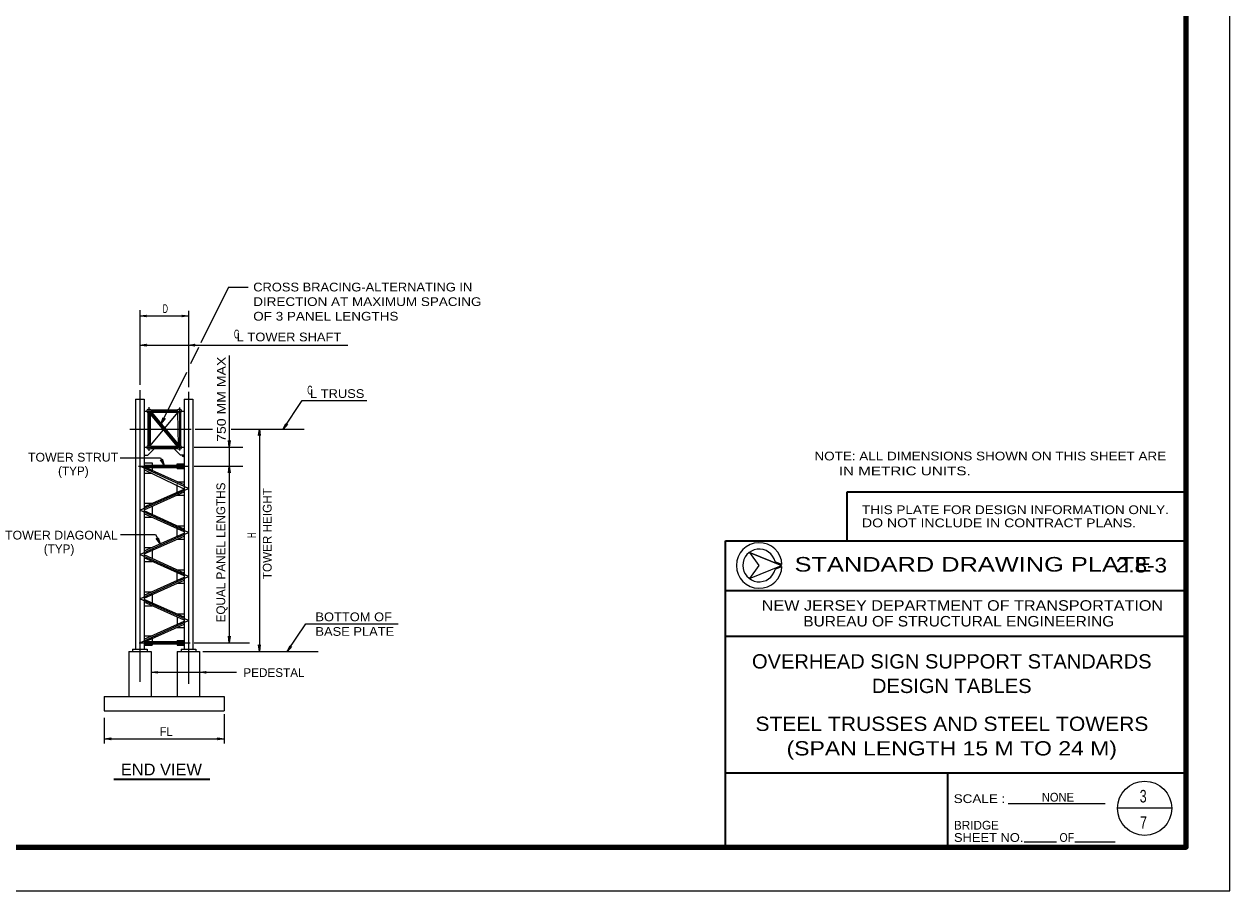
# Model space of a CAD drawing. Extents: x 312601.858 to 312602.699, y 144420.11 to 144420.704.
# Drawn here: x 312602.2859 to 312602.6989, y 144420.1096 to 144420.4066 of the extents above; entities that cross this region are included whole.
import ezdxf
from ezdxf.enums import TextEntityAlignment as Align

# ---------------------------------------------------------------- set-up
doc = ezdxf.new("R2010")
doc.units = 0
doc.header["$LTSCALE"] = 0.0012
doc.header["$PDMODE"] = 32
doc.header["$PDSIZE"] = 0.0006
doc.linetypes.add('DOT_DASHED', pattern=[7.7, 5, -1.2, 0.3, -1.2])
doc.linetypes.add('LONG_DASHED', pattern=[7.5, 6, -1.5])
for name, color, linetype, lineweight in [('1', 7, 'Continuous', 25), ('2', 7, 'Continuous', 13), ('39', 7, 'Continuous', 13)]:
    doc.layers.add(name, color=color, linetype=linetype, lineweight=lineweight)
doc.layers.add('51', color=7, linetype='Continuous')

msp = doc.modelspace()

# ---------------------------------------------------------------- hatches: boundary and pattern name
at = {"layer": '39'}
for points in [[(312602.3276, 144420.3066), (312602.3278, 144420.3063), (312602.3256, 144420.3066), (312602.3278, 144420.3069)], [(312602.3402, 144420.3066), (312602.34, 144420.3069), (312602.3422, 144420.3066), (312602.34, 144420.3063)], [(312602.3276, 144420.2966), (312602.3278, 144420.2963), (312602.3256, 144420.2966), (312602.3278, 144420.2969)], [(312602.3442, 144420.2966), (312602.3444, 144420.2963), (312602.3422, 144420.2966), (312602.3444, 144420.2969)], [(312602.3338, 144420.2715), (312602.3342, 144420.2715), (312602.3329, 144420.2697), (312602.3336, 144420.2718)], [(312602.3757, 144420.2695), (312602.3761, 144420.2695), (312602.3746, 144420.2678), (312602.3756, 144420.2698)], [(312602.333, 144420.2573), (312602.3332, 144420.2576), (312602.3339, 144420.2555), (312602.3326, 144420.2573)], [(312602.333, 144420.2573), (312602.3332, 144420.2576), (312602.3339, 144420.2555), (312602.3326, 144420.2573)], [(312602.3316, 144420.2303), (312602.3318, 144420.2306), (312602.3325, 144420.2285), (312602.3312, 144420.2303)], [(312602.3771, 144420.1933), (312602.3775, 144420.1933), (312602.376, 144420.1916), (312602.377, 144420.1936)], [(312602.3314, 144420.1845), (312602.3316, 144420.1842), (312602.3294, 144420.1845), (312602.3316, 144420.1848)], [(312602.348, 144420.1845), (312602.3482, 144420.1842), (312602.346, 144420.1845), (312602.3482, 144420.1848)]]:
    msp.add_hatch(color=256, dxfattribs=at).paths.add_polyline_path(points)

# ---------------------------------------------------------------- linework, layer by layer
at = {"layer": '1', "lineweight": 13}
for p, q in [((312602.3559, 144420.3165), (312602.3465, 144420.2974)), ((312602.3559, 144420.3165), (312602.3627, 144420.3165)), ((312602.3256, 144420.3086), (312602.3256, 144420.283)), ((312602.3422, 144420.3084), (312602.3422, 144420.2822)), ((312602.3457, 144420.2958), (312602.3429, 144420.2902)), ((312602.3415, 144420.2872), (312602.3329, 144420.2697)), ((312602.3221, 144420.2678), (312602.33, 144420.2678)), ((312602.3445, 144420.2678), (312602.3505, 144420.2678)), ((312602.3568, 144420.2678), (312602.3819, 144420.2678)), ((312602.3571, 144420.2678), (312602.3585, 144420.2678)), ((312602.3665, 144420.2678), (312602.3665, 144420.1916)), ((312602.3442, 144420.2616), (312602.3608, 144420.2616)), ((312602.3326, 144420.258), (312602.3339, 144420.2555)), ((312602.3442, 144420.2551), (312602.3608, 144420.2551)), ((312602.3189, 144420.2317), (312602.3309, 144420.2317)), ((312602.3309, 144420.2317), (312602.3325, 144420.2286)), ((312602.5432, 144420.2198), (312602.5455, 144420.2208)), ((312602.3442, 144420.1946), (312602.3631, 144420.1946)), ((312602.3471, 144420.1916), (312602.3866, 144420.1916)), ((312602.3294, 144420.1845), (312602.3587, 144420.1845)), ((312602.3544, 144420.1702), (312602.3544, 144420.1601)), ((312602.3134, 144420.1689), (312602.3134, 144420.1601)), ((312602.3544, 144420.1694), (312602.3544, 144420.1685)), ((312602.3134, 144420.1617), (312602.3544, 144420.1617)), ((312602.6285, 144420.1264), (312602.6395, 144420.1264)), ((312602.6458, 144420.1264), (312602.6596, 144420.1264))]:
    msp.add_line(p, q, dxfattribs=at)
at = {"layer": '1'}
for p, q in [((312602.3241, 144420.2781), (312602.3241, 144420.1924)), ((312602.3241, 144420.2781), (312602.3271, 144420.2781)), ((312602.3271, 144420.2781), (312602.3271, 144420.1924)), ((312602.3407, 144420.2781), (312602.3407, 144420.1924)), ((312602.3407, 144420.2781), (312602.3437, 144420.2781)), ((312602.3437, 144420.2781), (312602.3437, 144420.1924)), ((312602.3283, 144420.2734), (312602.3283, 144420.2622)), ((312602.3291, 144420.2734), (312602.3291, 144420.2622)), ((312602.3293, 144420.2744), (312602.3385, 144420.2744)), ((312602.3296, 144420.2736), (312602.3387, 144420.2627)), ((312602.3395, 144420.2734), (312602.3395, 144420.2622)), ((312602.3291, 144420.2729), (312602.3382, 144420.262)), ((312602.3293, 144420.262), (312602.3385, 144420.262)), ((312602.3293, 144420.2612), (312602.3385, 144420.2612)), ((312602.3271, 144420.2563), (312602.3298, 144420.2563)), ((312602.3271, 144420.2555), (312602.3407, 144420.2555)), ((312602.3271, 144420.2547), (312602.3407, 144420.2547)), ((312602.3271, 144420.2527), (312602.3297, 144420.2527)), ((312602.3407, 144420.2487), (312602.3275, 144420.2547)), ((312602.3298, 144420.2563), (312602.3298, 144420.2555)), ((312602.3298, 144420.2547), (312602.3298, 144420.2537)), ((312602.3383, 144420.2559), (312602.3407, 144420.2559)), ((312602.3383, 144420.2555), (312602.3383, 144420.2559)), ((312602.3383, 144420.2543), (312602.3383, 144420.2547)), ((312602.3383, 144420.2543), (312602.3407, 144420.2543)), ((312602.3383, 144420.2498), (312602.3407, 144420.2498)), ((312602.3383, 144420.2462), (312602.3383, 144420.2488)), ((312602.3271, 144420.2402), (312602.3407, 144420.2463)), ((312602.3383, 144420.2452), (312602.3407, 144420.2452)), ((312602.3271, 144420.2424), (312602.3298, 144420.2424)), ((312602.3298, 144420.2414), (312602.3298, 144420.2386)), ((312602.3407, 144420.2336), (312602.3271, 144420.2398)), ((312602.3407, 144420.2326), (312602.3271, 144420.2388)), ((312602.3271, 144420.2376), (312602.3298, 144420.2376)), ((312602.3271, 144420.2261), (312602.3407, 144420.2322)), ((312602.3383, 144420.2347), (312602.3407, 144420.2347)), ((312602.3383, 144420.2311), (312602.3383, 144420.2337)), ((312602.3271, 144420.2251), (312602.3407, 144420.2312)), ((312602.3383, 144420.2301), (312602.3407, 144420.2301)), ((312602.3271, 144420.2273), (312602.3298, 144420.2273)), ((312602.3407, 144420.2185), (312602.3271, 144420.2247)), ((312602.3407, 144420.2175), (312602.3271, 144420.2237)), ((312602.3298, 144420.2263), (312602.3298, 144420.2235)), ((312602.3271, 144420.2225), (312602.3298, 144420.2225)), ((312602.3383, 144420.2196), (312602.3407, 144420.2196)), ((312602.3271, 144420.2109), (312602.3407, 144420.2171)), ((312602.3271, 144420.2099), (312602.3407, 144420.2161)), ((312602.3383, 144420.216), (312602.3383, 144420.2186)), ((312602.3271, 144420.2121), (312602.3298, 144420.2121)), ((312602.3383, 144420.215), (312602.3407, 144420.215)), ((312602.3407, 144420.2034), (312602.3271, 144420.2095)), ((312602.3407, 144420.2024), (312602.3271, 144420.2085)), ((312602.3271, 144420.2073), (312602.3298, 144420.2073)), ((312602.3298, 144420.2111), (312602.3298, 144420.2083)), ((312602.3383, 144420.2045), (312602.3407, 144420.2045)), ((312602.3383, 144420.2035), (312602.3383, 144420.2009)), ((312602.3271, 144420.1958), (312602.3407, 144420.202)), ((312602.3275, 144420.195), (312602.3407, 144420.201)), ((312602.3383, 144420.1999), (312602.3407, 144420.1999)), ((312602.3271, 144420.197), (312602.3298, 144420.197)), ((312602.3271, 144420.195), (312602.3407, 144420.195)), ((312602.3298, 144420.196), (312602.3298, 144420.195)), ((312602.3383, 144420.1954), (312602.3407, 144420.1954)), ((312602.3383, 144420.1954), (312602.3383, 144420.195)), ((312602.3218, 144420.1916), (312602.3218, 144420.1762)), ((312602.3218, 144420.1916), (312602.3294, 144420.1916)), ((312602.3231, 144420.1924), (312602.3231, 144420.1916)), ((312602.3231, 144420.1924), (312602.3281, 144420.1924)), ((312602.3271, 144420.1942), (312602.3407, 144420.1942)), ((312602.3271, 144420.1938), (312602.3298, 144420.1938)), ((312602.3281, 144420.1924), (312602.3281, 144420.1916)), ((312602.3294, 144420.1916), (312602.3294, 144420.1762)), ((312602.3298, 144420.1942), (312602.3298, 144420.1938)), ((312602.3383, 144420.1942), (312602.3383, 144420.1938)), ((312602.3383, 144420.1938), (312602.3407, 144420.1938)), ((312602.3384, 144420.1916), (312602.3384, 144420.1762)), ((312602.3384, 144420.1916), (312602.346, 144420.1916)), ((312602.3397, 144420.1924), (312602.3397, 144420.1916)), ((312602.3397, 144420.1924), (312602.3447, 144420.1924)), ((312602.3447, 144420.1924), (312602.3447, 144420.1916)), ((312602.346, 144420.1916), (312602.346, 144420.1762)), ((312602.3134, 144420.1762), (312602.3134, 144420.1713)), ((312602.3134, 144420.1762), (312602.3544, 144420.1762)), ((312602.3544, 144420.1762), (312602.3544, 144420.1713)), ((312602.3134, 144420.1713), (312602.3544, 144420.1713))]:
    msp.add_line(p, q, dxfattribs=at)
at = {"layer": '1', "linetype": 'DOT_DASHED', "lineweight": 13}
for p, q in [((312602.3256, 144420.2812), (312602.3256, 144420.1705)), ((312602.3422, 144420.2806), (312602.3422, 144420.1707)), ((312602.3271, 144420.274), (312602.3407, 144420.274)), ((312602.3287, 144420.2753), (312602.3287, 144420.2604)), ((312602.3287, 144420.274), (312602.3391, 144420.2616)), ((312602.3391, 144420.2752), (312602.3391, 144420.2605)), ((312602.3236, 144420.2678), (312602.3431, 144420.2678)), ((312602.3271, 144420.2616), (312602.3407, 144420.2616)), ((312602.3251, 144420.2551), (312602.3423, 144420.2551)), ((312602.3253, 144420.1946), (312602.3428, 144420.1946))]:
    msp.add_line(p, q, dxfattribs=at)
at = {"layer": '1', "linetype": 'LONG_DASHED', "lineweight": 13}
msp.add_line((312602.3291, 144420.2621), (312602.3386, 144420.2735), dxfattribs=at)
at = {"layer": '1', "lineweight": 13}
for points in [[(312602.3562, 144420.293), (312602.3562, 144420.2551), (312602.3562, 144420.1946)], [(312602.5453, 144420.2211), (312602.5344, 144420.2256), (312602.5453, 144420.2211)], [(312602.5455, 144420.2214), (312602.5432, 144420.2224), (312602.5431, 144420.2224)]]:
    msp.add_lwpolyline(points, dxfattribs=at)
at = {"layer": '1'}
for points in [[(312602.3293, 144420.2736), (312602.3385, 144420.2736), (312602.3387, 144420.2622)], [(312602.3271, 144420.2589), (312602.3283, 144420.2589), (312602.3306, 144420.2612)], [(312602.3407, 144420.2589), (312602.3395, 144420.2589), (312602.3372, 144420.2612)], [(312602.3271, 144420.2412), (312602.3407, 144420.2473), (312602.3271, 144420.2539)]]:
    msp.add_lwpolyline(points, dxfattribs=at)
at = {"layer": '1', "lineweight": 13}
for points in [[(312602.3662, 144420.2656), (312602.3665, 144420.2678), (312602.3668, 144420.2656), (312602.3665, 144420.2658)], [(312602.3565, 144420.2639), (312602.3562, 144420.2616), (312602.3559, 144420.2639), (312602.3562, 144420.2636)], [(312602.3559, 144420.2529), (312602.3562, 144420.2551), (312602.3565, 144420.2529), (312602.3562, 144420.2531)], [(312602.5453, 144420.2211), (312602.5344, 144420.2256), (312602.5376, 144420.2211), (312602.5344, 144420.2166)], [(312602.5376, 144420.2211), (312602.5344, 144420.2166), (312602.5453, 144420.2211), (312602.5344, 144420.2256)], [(312602.3565, 144420.1969), (312602.3562, 144420.1946), (312602.3559, 144420.1969), (312602.3562, 144420.1966)], [(312602.3668, 144420.1939), (312602.3665, 144420.1916), (312602.3662, 144420.1939), (312602.3665, 144420.1936)], [(312602.3157, 144420.1614), (312602.3134, 144420.1617), (312602.3157, 144420.162), (312602.3154, 144420.1617)], [(312602.3522, 144420.162), (312602.3544, 144420.1617), (312602.3522, 144420.1614), (312602.3524, 144420.1617)]]:
    msp.add_lwpolyline(points, close=True, dxfattribs=at)
at = {"layer": '1', "linetype": 'DOT_DASHED', "lineweight": 13}
msp.add_lwpolyline([(312602.3256, 144420.1946), (312602.3422, 144420.2022), (312602.3256, 144420.2097), (312602.3422, 144420.2173), (312602.3256, 144420.2249), (312602.3422, 144420.2324), (312602.3256, 144420.24), (312602.3422, 144420.2475), (312602.3256, 144420.2551)], dxfattribs=at)
at = {"layer": '1'}
for centre in [(312602.3287, 144420.274), (312602.3391, 144420.274), (312602.3287, 144420.2616), (312602.3391, 144420.2616)]:
    msp.add_circle(centre, 0.0007, dxfattribs=at)
at = {"layer": '1', "lineweight": 13}
for radius, start, end in [(0.0078026, 2.21392, 357.78608), (0.0056, 13.69411, 346.30589)]:
    msp.add_arc((312602.5377, 144420.2211), radius, start, end, dxfattribs=at)
at = {"layer": '1'}
msp.add_point((312602.3405, 144420.2586), dxfattribs=at)
at = {"layer": '2'}
for p, q in [((312602.3256, 144420.3066), (312602.3422, 144420.3066)), ((312602.3188, 144420.258), (312602.3326, 144420.258))]:
    msp.add_line(p, q, dxfattribs=at)
at = {"layer": '2', "lineweight": 35}
msp.add_line((312602.3167, 144420.1479), (312602.3495, 144420.1479), dxfattribs=at)
at = {"layer": '2'}
for points in [[(312602.3256, 144420.2966), (312602.3422, 144420.2966), (312602.3968, 144420.2966)], [(312602.3746, 144420.2678), (312602.3812, 144420.2776), (312602.4033, 144420.2776)], [(312602.376, 144420.1916), (312602.3824, 144420.2011), (312602.414, 144420.2011)]]:
    msp.add_lwpolyline(points, dxfattribs=at)
at = {"layer": '39', "lineweight": 35}
for p, q in [((312602.5678, 144420.2463), (312602.6839, 144420.2463)), ((312602.5678, 144420.2296), (312602.5678, 144420.2463)), ((312602.5261, 144420.1246), (312602.5261, 144420.2296)), ((312602.5261, 144420.2296), (312602.6839, 144420.2296)), ((312602.6839, 144420.2296), (312602.6839, 144420.1246)), ((312602.5261, 144420.2125), (312602.6839, 144420.2125)), ((312602.5261, 144420.1969), (312602.6839, 144420.1969)), ((312602.5261, 144420.15), (312602.6839, 144420.15)), ((312602.6023, 144420.1249), (312602.6023, 144420.15))]:
    msp.add_line(p, q, dxfattribs=at)
at = {"layer": '39'}
for p, q in [((312602.6023, 144420.15), (312602.6839, 144420.15)), ((312602.623, 144420.1396), (312602.6562, 144420.1396))]:
    msp.add_line(p, q, dxfattribs=at)
at = {"layer": '39', "lineweight": 25}
for p, q in [((312602.679, 144420.1379), (312602.6604, 144420.1379)), ((312602.4521, 144420.1246), (312602.6839, 144420.1246))]:
    msp.add_line(p, q, dxfattribs=at)
msp.add_lwpolyline([(312601.8579, 144420.1096), (312602.6989, 144420.1096), (312602.6989, 144420.7036)], dxfattribs=at)
at = {"layer": '39', "lineweight": 158}
msp.add_lwpolyline([(312601.9089, 144420.1246), (312602.6839, 144420.1246), (312602.6839, 144420.6646)], dxfattribs=at)
at = {"layer": '39'}
for points in [[(312602.3276, 144420.3066), (312602.3278, 144420.3063), (312602.3256, 144420.3066), (312602.3278, 144420.3069)], [(312602.3402, 144420.3066), (312602.34, 144420.3069), (312602.3422, 144420.3066), (312602.34, 144420.3063)], [(312602.3276, 144420.2966), (312602.3278, 144420.2963), (312602.3256, 144420.2966), (312602.3278, 144420.2969)], [(312602.3442, 144420.2966), (312602.3444, 144420.2963), (312602.3422, 144420.2966), (312602.3444, 144420.2969)], [(312602.3338, 144420.2715), (312602.3342, 144420.2715), (312602.3329, 144420.2697), (312602.3336, 144420.2718)], [(312602.3757, 144420.2695), (312602.3761, 144420.2695), (312602.3746, 144420.2678), (312602.3756, 144420.2698)], [(312602.333, 144420.2573), (312602.3332, 144420.2576), (312602.3339, 144420.2555), (312602.3326, 144420.2573)], [(312602.333, 144420.2573), (312602.3332, 144420.2576), (312602.3339, 144420.2555), (312602.3326, 144420.2573)], [(312602.3316, 144420.2303), (312602.3318, 144420.2306), (312602.3325, 144420.2285), (312602.3312, 144420.2303)], [(312602.5453, 144420.2211), (312602.5344, 144420.2256), (312602.5376, 144420.2211), (312602.5344, 144420.2166)], [(312602.3771, 144420.1933), (312602.3775, 144420.1933), (312602.376, 144420.1916), (312602.377, 144420.1936)], [(312602.3314, 144420.1845), (312602.3316, 144420.1842), (312602.3294, 144420.1845), (312602.3316, 144420.1848)], [(312602.348, 144420.1845), (312602.3482, 144420.1842), (312602.346, 144420.1845), (312602.3482, 144420.1848)]]:
    msp.add_lwpolyline(points, close=True, dxfattribs=at)
at = {"layer": '39', "lineweight": 25}
msp.add_circle((312602.6697, 144420.1379), 0.0093005, dxfattribs=at)

# ---------------------------------------------------------------- texts
at = {"layer": '1'}
for s, width, p in [('NOTE: ALL DIMENSIONS SHOWN ON THIS SHEET ARE', 1.15, (312602.5566, 144420.2571)), ('     IN METRIC UNITS.', 1.3, (312602.5577, 144420.252)), ('TOWER DIAGONAL', 1.05, (312602.2794, 144420.23))]:
    msp.add_text(s, height=0.003, dxfattribs=dict(at, width=width)).set_placement(p)
msp.add_text('TOWER HEIGHT', height=0.003, rotation=90, dxfattribs=at).set_placement((312602.3707, 144420.232), align=Align.CENTER)
at = {"layer": '1', "width": 0.95}
for s, p in [('FL', (312602.3346, 144420.1627)), ('NONE', (312602.64, 144420.1402))]:
    msp.add_text(s, height=0.003, dxfattribs=at).set_placement(p, align=Align.CENTER)
at = {"layer": '2'}
for s, width, p in [('CROSS BRACING-ALTERNATING IN', 1.1, (312602.3644, 144420.315)), ('DIRECTION AT MAXIMUM SPACING', 1.15, (312602.3644, 144420.31)), ('OF 3 PANEL LENGTHS', 1.15, (312602.3644, 144420.305)), ('THIS PLATE FOR DESIGN INFORMATION ONLY.', 1.15, (312602.5729, 144420.2387)), ('DO NOT INCLUDE IN CONTRACT PLANS.', 1.2, (312602.5729, 144420.2342)), ('BOTTOM OF', 1.1, (312602.3857, 144420.202)), ('BASE PLATE', 1.1, (312602.3857, 144420.197))]:
    msp.add_text(s, height=0.003, dxfattribs=dict(at, width=width)).set_placement(p)
for s, height, width, p in [('D', 0.003, 0.6, (312602.3343, 144420.3076)), ('C', 0.003, 0.6, (312602.3587, 144420.2989)), ('L TOWER SHAFT', 0.003, 1.1, (312602.37665, 144420.2979)), ('C', 0.003, 0.6, (312602.3838, 144420.2797)), ('L TRUSS', 0.003, 1.1, (312602.39315, 144420.2785)), ('TOWER STRUT', 0.003, 1.05, (312602.3027, 144420.2567)), ('2.8-3', 0.005, 1.15, (312602.6686, 144420.2187)), ('OVERHEAD SIGN SUPPORT STANDARDS', 0.0049, 1.05, (312602.60365, 144420.1858)), ('DESIGN TABLES', 0.0049, 1.05, (312602.60365, 144420.1774)), ('STEEL TRUSSES AND STEEL TOWERS', 0.0049, 1.1, (312602.6037, 144420.1644)), ('(SPAN LENGTH 15 M TO 24 M)', 0.0049, 1.2, (312602.60365, 144420.156)), ('END VIEW', 0.004, 1.05, (312602.33295, 144420.1492))]:
    msp.add_text(s, height=height, dxfattribs=dict(at, width=width)).set_placement(p, align=Align.CENTER)
for s, height, width, p in [('750 MM MAX', 0.003, 1.2, (312602.355, 144420.27805)), ('H', 0.002998, 0.6, (312602.3654, 144420.23145))]:
    msp.add_text(s, height=height, rotation=90, dxfattribs=dict(at, width=width)).set_placement(p, align=Align.CENTER)
for s, p in [('(TYP)', (312602.3028, 144420.252)), ('(TYP)', (312602.2979, 144420.2253)), ('PEDESTAL', (312602.3715, 144420.1829))]:
    msp.add_text(s, height=0.003, dxfattribs=at).set_placement(p, align=Align.CENTER)
msp.add_text('EQUAL PANEL LENGTHS', height=0.003, rotation=90, dxfattribs=at).set_placement((312602.3548, 144420.22555), align=Align.CENTER)
at = {"layer": '39'}
for s, height, width, p in [('STANDARD DRAWING PLATE       ', 0.005, 1.3, (312602.61935, 144420.219)), ('NEW JERSEY DEPARTMENT OF TRANSPORTATION', 0.003599, 1.15, (312602.6073, 144420.2056)), ('BUREAU OF STRUCTURAL ENGINEERING', 0.0036, 1.1, (312602.60605, 144420.2002)), ('SCALE :', 0.003, 1.15, (312602.61315, 144420.1397)), ('OF', 0.003, 0.9, (312602.64305, 144420.1264))]:
    msp.add_text(s, height=height, dxfattribs=dict(at, width=width)).set_placement(p, align=Align.CENTER)
msp.add_text('BRIDGE', height=0.003, dxfattribs=at).set_placement((312602.6044, 144420.1306))
at = {"layer": '39', "width": 1.1}
msp.add_text('SHEET NO.', height=0.003, dxfattribs=at).set_placement((312602.6044, 144420.1264))
at = {"layer": '51', "width": 0.75}
for s, p in [('3', (312602.6692, 144420.1399)), ('7', (312602.6693, 144420.1309))]:
    msp.add_text(s, height=0.0043, dxfattribs=at).set_placement(p, align=Align.CENTER)

doc.saveas('drawing.dxf')
